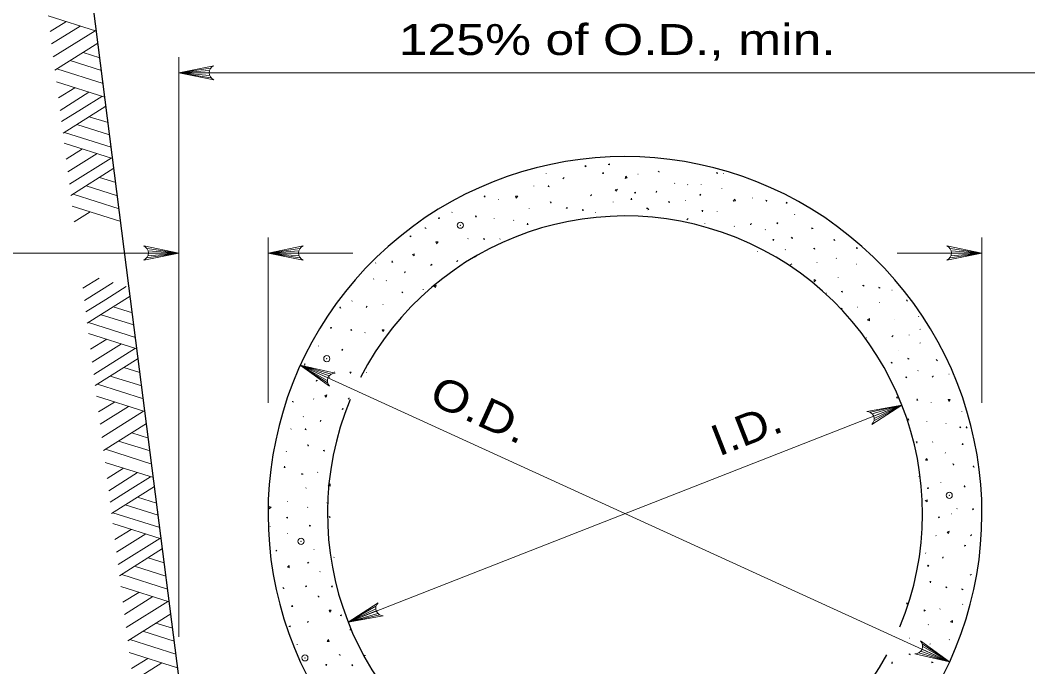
# Model space of a CAD drawing. Extents: x 1083.1 to 1117.1, y 697.4 to 741.4.
# Drawn here: x 1089.62 to 1094.7, y 722.98 to 726.24 of the extents above; entities that cross this region are included whole.
import ezdxf
from ezdxf.enums import TextEntityAlignment as Align

# ---------------------------------------------------------------- set-up
doc = ezdxf.new("R2010")
doc.units = 0
doc.header["$LTSCALE"] = 0.062
doc.header["$PDMODE"] = 32
doc.header["$PDSIZE"] = 0.031
doc.layers.add('1', color=7, linetype='Continuous', lineweight=13)

msp = doc.modelspace()

# ---------------------------------------------------------------- linework, layer by layer
at = {"layer": '1'}
for p, q in [((1090.00183, 726.18108), (1089.758, 726.25825)), ((1089.84842, 726.22842), (1089.76825, 726.17892)), ((1089.91933, 726.20692), (1089.776, 726.1175)), ((1089.995, 726.18325), (1089.7845, 726.051)), ((1090.0095, 726.12108), (1089.793, 725.9845)), ((1090.01892, 726.0475), (1089.93492, 726.07375)), ((1090.02725, 725.98242), (1089.869, 726.03267)), ((1090.41717, 723.12875), (1090.41717, 726.05008)), ((1090.03558, 725.91667), (1089.80308, 725.99083)), ((1090.57733, 725.99383), (1090.41717, 725.97142)), ((1090.57192, 725.98275), (1090.41717, 725.97142)), ((1090.41717, 725.97142), (1094.915, 725.97142)), ((1090.57025, 725.97142), (1090.41717, 725.97142)), ((1090.57308, 725.95708), (1090.41717, 725.97142)), ((1090.57925, 725.94667), (1090.41717, 725.97142)), ((1090.04442, 725.848), (1089.80058, 725.92517)), ((1089.89375, 725.89567), (1089.81092, 725.84442)), ((1089.96417, 725.87342), (1089.81892, 725.78158)), ((1090.02933, 725.85267), (1089.92708, 725.78808)), ((1089.92708, 725.78808), (1089.82608, 725.72508)), ((1090.05, 725.80375), (1089.8335, 725.66783)), ((1090.0685, 725.65933), (1089.90275, 725.71092)), ((1090.06067, 725.72008), (1089.96467, 725.75)), ((1090.0765, 725.59642), (1089.84033, 725.67092)), ((1090.08375, 725.53925), (1089.83933, 725.61633)), ((1089.93233, 725.5875), (1089.85017, 725.53642)), ((1090.00583, 725.56417), (1089.8585, 725.472)), ((1090.07617, 725.54192), (1089.86642, 725.40983)), ((1090.09, 725.49075), (1089.87358, 725.35342)), ((1092.26942, 725.464), (1092.26875, 725.462)), ((1092.73292, 725.45967), (1092.73092, 725.46033)), ((1093.16183, 725.46317), (1093.16267, 725.46167)), ((1093.16267, 725.46167), (1093.163, 725.46283)), ((1090.10767, 725.352), (1089.94958, 725.40158)), ((1090.09917, 725.41917), (1090.01742, 725.44433)), ((1092.20708, 725.40167), (1092.20642, 725.39967)), ((1092.91617, 725.41508), (1092.91808, 725.41425)), ((1092.98142, 725.40608), (1092.98208, 725.40808)), ((1093.05008, 725.40625), (1093.05075, 725.40817)), ((1090.11608, 725.28625), (1089.88442, 725.35983)), ((1093.15392, 725.38625), (1093.15475, 725.38817)), ((1090.12425, 725.22267), (1089.8805, 725.29975)), ((1092.02908, 725.33508), (1092.02833, 725.33308)), ((1092.6065, 725.31925), (1092.60583, 725.32125)), ((1092.971, 725.32525), (1092.97175, 725.32725)), ((1093.3085, 725.33933), (1093.30917, 725.34133)), ((1089.97075, 725.26983), (1089.89058, 725.22042)), ((1091.79392, 725.26683), (1091.79458, 725.26875)), ((1092.18358, 725.28817), (1092.18283, 725.28625)), ((1092.51875, 725.26792), (1092.51675, 725.26725)), ((1092.78142, 725.28075), (1092.78625, 725.2825)), ((1093.13042, 725.27275), (1093.13117, 725.27475)), ((1093.52108, 725.25625), (1093.52175, 725.25825)), ((1092.00742, 725.23775), (1092.00658, 725.23583)), ((1092.10383, 725.22725), (1092.10533, 725.2285)), ((1093.06808, 725.21042), (1093.06875, 725.21242)), ((1093.21875, 725.1985), (1093.21717, 725.19725)), ((1093.37492, 725.18133), (1093.37342, 725.18008)), ((1090.86692, 724.30833), (1090.86692, 725.14183)), ((1091.87467, 725.13483), (1091.87542, 725.13675)), ((1092.03608, 725.133), (1092.03675, 725.135)), ((1094.46525, 724.30833), (1094.46525, 725.14183)), ((1090.41717, 725.06317), (1087.8435, 725.06317)), ((1090.255, 725.03842), (1090.41717, 725.06317)), ((1090.25692, 725.08558), (1090.41717, 725.06317)), ((1090.26117, 725.04875), (1090.41717, 725.06317)), ((1090.26233, 725.0745), (1090.41717, 725.06317)), ((1090.264, 725.06317), (1090.41717, 725.06317)), ((1091.02717, 725.08558), (1090.86692, 725.06317)), ((1091.02175, 725.0745), (1090.86692, 725.06317)), ((1091.29375, 725.06317), (1090.86692, 725.06317)), ((1091.02008, 725.06317), (1090.86692, 725.06317)), ((1091.02292, 725.04875), (1090.86692, 725.06317)), ((1091.02908, 725.03842), (1090.86692, 725.06317)), ((1093.33392, 725.06925), (1093.33475, 725.07117)), ((1093.47517, 725.08108), (1093.474, 725.07958)), ((1094.03808, 725.06317), (1094.46525, 725.06317)), ((1094.30308, 725.03842), (1094.46525, 725.06317)), ((1094.305, 725.08558), (1094.46525, 725.06317)), ((1094.30925, 725.04875), (1094.46525, 725.06317)), ((1094.31042, 725.0745), (1094.46525, 725.06317)), ((1094.31208, 725.06317), (1094.46525, 725.06317)), ((1091.40983, 725.01358), (1091.40908, 725.01158)), ((1093.63325, 725.01458), (1093.63525, 725.01533)), ((1093.73058, 725.03625), (1093.7325, 725.03708)), ((1093.83533, 725.00767), (1093.83333, 725.00692)), ((1090.01608, 724.93717), (1089.93325, 724.88583)), ((1090.0865, 724.91483), (1089.94133, 724.823)), ((1090.15167, 724.89417), (1090.04942, 724.8295)), ((1091.3995, 724.93267), (1091.39875, 724.93075)), ((1091.46475, 724.92375), (1091.46275, 724.92442)), ((1093.74108, 724.93983), (1093.73983, 724.93833)), ((1090.17242, 724.84517), (1089.95583, 724.70933)), ((1091.64792, 724.87917), (1091.64992, 724.8785)), ((1093.68017, 724.86008), (1093.68208, 724.86092)), ((1094.0135, 724.87625), (1094.0115, 724.87558)), ((1090.04942, 724.8295), (1089.94858, 724.7665)), ((1090.183, 724.76167), (1090.087, 724.79142)), ((1091.28983, 724.8205), (1091.29133, 724.82158)), ((1091.44608, 724.80333), (1091.4475, 724.80442)), ((1093.95125, 724.81392), (1093.94925, 724.81325)), ((1090.19083, 724.70083), (1090.02508, 724.75233)), ((1093.83775, 724.79042), (1093.83575, 724.78958)), ((1094.146, 724.74433), (1094.14667, 724.74233)), ((1090.19883, 724.63792), (1089.96267, 724.71233)), ((1091.53433, 724.72908), (1091.53358, 724.72708)), ((1094.0255, 724.72567), (1094.02667, 724.72717)), ((1090.20617, 724.58075), (1089.96167, 724.65783)), ((1091.35625, 724.66242), (1091.35558, 724.6605)), ((1094.09892, 724.65142), (1094.09808, 724.6495)), ((1094.15483, 724.67908), (1094.153, 724.67825)), ((1090.05467, 724.629), (1089.97267, 724.57783)), ((1090.12817, 724.60567), (1089.98083, 724.5135)), ((1091.12108, 724.59417), (1091.12183, 724.59617)), ((1093.88458, 724.63592), (1093.88267, 724.63517)), ((1094.15475, 724.61042), (1094.15275, 724.60958)), ((1090.1985, 724.58342), (1089.98875, 724.45133)), ((1094.04275, 724.56942), (1094.04383, 724.57092)), ((1090.21233, 724.53217), (1089.99592, 724.39483)), ((1094.3025, 723.00258), (1091.02967, 724.49792)), ((1091.16908, 724.43458), (1091.02967, 724.49792)), ((1091.16575, 724.42033), (1091.02967, 724.49792)), ((1091.16708, 724.40833), (1091.02967, 724.49792)), ((1091.17533, 724.44425), (1091.02967, 724.49792)), ((1091.18483, 724.45208), (1091.02967, 724.49792)), ((1090.23008, 724.39342), (1090.07192, 724.443)), ((1090.2215, 724.46067), (1090.13983, 724.48592)), ((1091.17667, 724.43742), (1091.17517, 724.43625)), ((1091.20183, 724.46208), (1091.20258, 724.46408)), ((1091.36325, 724.46033), (1091.364, 724.46233)), ((1094.14283, 724.46917), (1094.1445, 724.47042)), ((1094.29908, 724.452), (1094.30058, 724.45325)), ((1090.2385, 724.32767), (1090.00675, 724.40133)), ((1090.24658, 724.26417), (1090.00283, 724.34125)), ((1090.09308, 724.31142), (1090.01292, 724.26192)), ((1090.16417, 724.28992), (1090.02083, 724.2005)), ((1091.09642, 724.32758), (1091.09842, 724.32692)), ((1091.27, 723.2035), (1094.062, 724.297)), ((1093.90208, 724.26067), (1094.062, 724.297)), ((1093.91158, 724.25325), (1094.062, 724.297)), ((1093.9195, 724.24092), (1094.062, 724.297)), ((1093.92108, 724.21742), (1094.062, 724.297)), ((1093.92208, 724.22975), (1094.062, 724.297)), ((1094.20942, 724.31117), (1094.20867, 724.30917)), ((1090.23983, 724.26608), (1090.02933, 724.13392)), ((1091.04517, 724.23983), (1091.04442, 724.23783)), ((1094.36383, 724.26425), (1094.36317, 724.26233)), ((1090.25417, 724.20408), (1090.03767, 724.06742)), ((1094.18775, 724.21383), (1094.18692, 724.21192)), ((1094.28408, 724.20333), (1094.28567, 724.20458)), ((1090.26367, 724.13042), (1090.17967, 724.15675)), ((1090.98275, 724.1775), (1090.98208, 724.1755)), ((1090.272, 724.06542), (1090.11367, 724.11575)), ((1094.21633, 724.10908), (1094.217, 724.11108)), ((1090.28042, 723.99967), (1090.04783, 724.07383)), ((1090.95925, 724.06392), (1090.9585, 724.062)), ((1094.28075, 724.05725), (1094.28, 724.05525)), ((1090.28908, 723.931), (1090.04533, 724.00817)), ((1090.13842, 723.97858), (1090.05558, 723.92742)), ((1090.20883, 723.95642), (1090.06367, 723.86442)), ((1090.274, 723.93558), (1090.17183, 723.87108)), ((1091.1185, 723.95792), (1091.11658, 723.95708)), ((1094.14675, 723.9365), (1094.14758, 723.9385)), ((1090.29475, 723.88675), (1090.07817, 723.75083)), ((1091.05767, 723.87817), (1091.05883, 723.87967)), ((1094.25808, 723.90592), (1094.25883, 723.90783)), ((1090.17183, 723.87108), (1090.07092, 723.808)), ((1090.3055, 723.80308), (1090.20933, 723.833)), ((1090.31317, 723.74233), (1090.14758, 723.79383)), ((1090.96333, 723.81025), (1090.96533, 723.81108)), ((1091.06808, 723.78167), (1091.06625, 723.78092)), ((1091.1655, 723.80342), (1091.1635, 723.80267)), ((1094.33892, 723.77383), (1094.33958, 723.77583)), ((1090.32125, 723.6795), (1090.08508, 723.75392)), ((1094.31367, 723.74908), (1094.31208, 723.74792)), ((1090.32858, 723.62217), (1090.084, 723.69925)), ((1090.177, 723.6705), (1090.095, 723.61933)), ((1090.2505, 723.64717), (1090.10317, 723.55492)), ((1090.32083, 723.62492), (1090.11108, 723.49275)), ((1090.96508, 723.649), (1090.96708, 723.64967)), ((1094.23342, 723.63942), (1094.23533, 723.63858)), ((1090.33475, 723.57358), (1090.11833, 723.43633)), ((1090.34383, 723.50217), (1090.26217, 723.52733)), ((1091.09717, 723.56825), (1091.09908, 723.56892)), ((1091.20058, 723.52992), (1091.19933, 723.52842)), ((1094.18217, 723.5515), (1094.18133, 723.5495)), ((1090.35242, 723.435), (1090.19425, 723.4845)), ((1090.36083, 723.36925), (1090.12917, 723.44283)), ((1091.12783, 723.45692), (1091.12975, 723.45767)), ((1090.36892, 723.30558), (1090.12517, 723.38275)), ((1090.21542, 723.35283), (1090.13525, 723.30342)), ((1090.2865, 723.33133), (1090.14317, 723.24192)), ((1090.36217, 723.30767), (1090.15167, 723.17542)), ((1091.41108, 723.28275), (1091.27, 723.2035)), ((1091.41008, 723.27042), (1091.27, 723.2035)), ((1094.2555, 723.26958), (1094.25358, 723.26883)), ((1094.36908, 723.29317), (1094.36708, 723.29242)), ((1090.37667, 723.2455), (1090.16017, 723.109)), ((1091.41267, 723.25933), (1091.27, 723.2035)), ((1091.42058, 723.24692), (1091.27, 723.2035)), ((1091.43008, 723.2395), (1091.27, 723.2035)), ((1090.386, 723.17192), (1090.302, 723.19825)), ((1094.19467, 723.18983), (1094.19575, 723.19133)), ((1090.40275, 723.04117), (1090.17025, 723.11525)), ((1090.39433, 723.10692), (1090.236, 723.15717)), ((1094.10042, 723.12208), (1094.10233, 723.12275)), ((1094.3025, 723.11517), (1094.3005, 723.11442)), ((1091.01425, 723.09133), (1091.01342, 723.08933)), ((1094.16317, 723.06625), (1094.3025, 723.00258)), ((1094.16533, 723.0925), (1094.3025, 723.00258)), ((1094.16658, 723.0805), (1094.3025, 723.00258)), ((1094.20517, 723.09342), (1094.20325, 723.09267)), ((1090.41142, 722.9725), (1090.16767, 723.04958)), ((1090.26083, 723.02017), (1090.178, 722.96883)), ((1094.14742, 723.04883), (1094.3025, 723.00258)), ((1094.157, 723.05667), (1094.3025, 723.00258)), ((1090.33125, 722.99783), (1090.186, 722.906))]:
    msp.add_line(p, q, dxfattribs=at)
at = {"layer": '1', "lineweight": 25}
msp.add_lwpolyline([(1090.41717, 722.92817), (1090.16583, 724.89717), (1089.94983, 726.58858)], dxfattribs=at)
at = {"layer": '1'}
for points in [[(1090.59417, 725.936), (1090.41717, 725.97142), (1090.59417, 726.00683)], [(1092.83917, 725.47083), (1092.83867, 725.47225), (1092.83367, 725.47633)], [(1092.35892, 725.44333), (1092.3575, 725.44275), (1092.35333, 725.43775)], [(1092.67025, 725.45), (1092.66667, 725.43833), (1092.67683, 725.44225), (1092.6705, 725.44992)], [(1092.49808, 725.35742), (1092.49742, 725.356), (1092.49242, 725.35183)], [(1092.61608, 725.38192), (1092.62775, 725.3855), (1092.62392, 725.37517), (1092.61617, 725.38167)], [(1092.82108, 725.36975), (1092.8225, 725.37042), (1092.82667, 725.37542)], [(1092.118, 725.3395), (1092.1255, 725.34942), (1092.1145, 725.34917), (1092.118, 725.33967)], [(1093.2195, 725.33492), (1093.212, 725.32508), (1093.223, 725.32525), (1093.21958, 725.33467)], [(1092.78642, 725.2825), (1092.7765, 725.29), (1092.77658, 725.28567)], [(1092.97858, 725.23108), (1092.98, 725.23167), (1092.98425, 725.23667)], [(1093.29767, 725.207), (1093.29908, 725.20758), (1093.30317, 725.21258)], [(1091.65825, 725.1915), (1091.65883, 725.19017), (1091.66383, 725.186)], [(1090.24017, 725.02775), (1090.41717, 725.06317), (1090.24017, 725.09858)], [(1091.04392, 725.02775), (1090.86692, 725.06317), (1091.04392, 725.09858)], [(1091.71675, 725.11017), (1091.72408, 725.12), (1091.71308, 725.11983), (1091.71658, 725.11033)], [(1094.28825, 725.02775), (1094.46525, 725.06317), (1094.28825, 725.09858)], [(1091.5945, 725.05617), (1091.60425, 725.04875), (1091.60417, 725.05975), (1091.59467, 725.05625)], [(1091.81767, 725.01975), (1091.81908, 725.02042), (1091.82317, 725.02525)], [(1093.50083, 725.00383), (1093.5015, 725.00517), (1093.5065, 725.00942)], [(1091.55967, 724.96892), (1091.55825, 724.96833), (1091.55417, 724.96342)], [(1091.71058, 724.88867), (1091.71425, 724.90042), (1091.70392, 724.89658), (1091.71042, 724.88883)], [(1093.62883, 724.92567), (1093.619, 724.91817), (1093.61908, 724.92917), (1093.62858, 724.92575)], [(1091.54158, 724.868), (1091.54217, 724.86658), (1091.54717, 724.86242)], [(1091.36708, 724.79483), (1091.36567, 724.79425), (1091.36158, 724.78925)], [(1094.09017, 724.82117), (1094.08883, 724.82183), (1094.08458, 724.82683)], [(1093.88908, 724.72483), (1093.89892, 724.73233), (1093.89867, 724.72133), (1093.88925, 724.72475)], [(1091.44525, 724.66692), (1091.45275, 724.67667), (1091.44175, 724.6765), (1091.44525, 724.66708)], [(1094.017, 724.64667), (1094.01642, 724.64533), (1094.01142, 724.64117)], [(1091.17617, 724.3925), (1091.02967, 724.49792), (1091.20542, 724.457)], [(1091.04942, 724.49967), (1091.05275, 724.49717), (1091.05267, 724.50692)], [(1094.24092, 724.52008), (1094.24033, 724.5215), (1094.23533, 724.52567)], [(1094.22025, 724.4435), (1094.21883, 724.44292), (1094.21467, 724.43792)], [(1091.15908, 724.33717), (1091.16267, 724.34883), (1091.15242, 724.345), (1091.15892, 724.33742)], [(1090.99008, 724.31642), (1090.99067, 724.31508), (1090.99567, 724.31092)], [(1091.27675, 724.33158), (1091.27533, 724.331), (1091.27108, 724.326)], [(1093.88433, 724.26508), (1094.062, 724.297), (1093.91025, 724.19925)], [(1094.29842, 724.31558), (1094.30583, 724.32542), (1094.29483, 724.32525), (1094.29833, 724.31583)], [(1091.13458, 724.21917), (1091.13317, 724.21858), (1091.129, 724.21358)], [(1094.18775, 724.02825), (1094.18033, 724.0185), (1094.19125, 724.01867), (1094.18783, 724.02808)], [(1091.16983, 723.89233), (1091.17967, 723.89983), (1091.17958, 723.88883), (1091.17008, 723.89225)], [(1090.8825, 723.78183), (1090.87275, 723.77433), (1090.87292, 723.78533), (1090.88233, 723.78183)], [(1094.17992, 723.81642), (1094.18975, 723.809), (1094.18958, 723.81992), (1094.18017, 723.8165)], [(1090.877, 723.68575), (1090.87725, 723.68525), (1090.87708, 723.68525)], [(1094.29608, 723.64892), (1094.29967, 723.66067), (1094.28942, 723.65675), (1094.29592, 723.64908)], [(1094.41375, 723.64325), (1094.41233, 723.64275), (1094.40817, 723.63775)], [(1090.90658, 723.56033), (1090.90708, 723.56175), (1090.91208, 723.56583)], [(1094.2715, 723.53083), (1094.27025, 723.53025), (1094.266, 723.52533)], [(1090.96425, 723.48075), (1090.97408, 723.48825), (1090.97383, 723.47725), (1090.96433, 723.48075)], [(1094.41075, 723.44492), (1094.41017, 723.4435), (1094.40517, 723.43933)], [(1090.94667, 723.3715), (1090.94608, 723.37283), (1090.94117, 723.377)], [(1091.11942, 723.33508), (1091.12, 723.33367), (1091.125, 723.32958)], [(1091.44775, 723.235), (1091.27, 723.2035), (1091.422, 723.30092)], [(1091.17775, 723.25367), (1091.18525, 723.2635), (1091.17425, 723.26342), (1091.17775, 723.25392)], [(1091.07125, 723.20625), (1091.06983, 723.20567), (1091.06575, 723.20075)], [(1091.27875, 723.16325), (1091.28008, 723.16383), (1091.28433, 723.16883)], [(1094.30692, 723.20417), (1094.31667, 723.2115), (1094.3165, 723.2005), (1094.30708, 723.204)], [(1091.17217, 723.11592), (1091.16475, 723.106), (1091.17575, 723.10617), (1091.17225, 723.11567)], [(1094.15625, 723.10833), (1094.3025, 723.00258), (1094.12683, 723.044)], [(1091.23067, 723.0345), (1091.23, 723.03583), (1091.22508, 723.04)]]:
    msp.add_lwpolyline(points, dxfattribs=at)
for points in [[(1092.47158, 725.50142), (1092.466, 725.50342), (1092.46525, 725.49808)], [(1092.58208, 725.51), (1092.58767, 725.508), (1092.58842, 725.51333)], [(1092.55608, 725.47), (1092.55808, 725.46442), (1092.55283, 725.46375)], [(1093.13017, 725.46242), (1093.13217, 725.468), (1093.12683, 725.46875)], [(1092.28092, 725.40317), (1092.27892, 725.39758), (1092.28425, 725.39675)], [(1091.95817, 725.35183), (1091.95617, 725.34617), (1091.9615, 725.3455)], [(1092.71317, 725.36708), (1092.71875, 725.36517), (1092.71958, 725.37042)], [(1093.04467, 725.36033), (1093.04275, 725.35467), (1093.048, 725.354)], [(1092.29283, 725.31408), (1092.29475, 725.31975), (1092.28958, 725.3205)], [(1092.69908, 725.33892), (1092.70092, 725.33333), (1092.69575, 725.33258)], [(1092.8885, 725.31558), (1092.89033, 725.32125), (1092.88508, 725.32192)], [(1093.37933, 725.32258), (1093.38133, 725.32825), (1093.376, 725.32892)], [(1093.48017, 725.31992), (1093.47825, 725.31433), (1093.48358, 725.31358)], [(1091.91392, 725.25175), (1091.912, 725.24617), (1091.91733, 725.24542)], [(1092.36883, 725.29133), (1092.37442, 725.29325), (1092.37508, 725.288)], [(1092.45783, 725.27942), (1092.45225, 725.27742), (1092.4515, 725.28275)], [(1093.05667, 725.27125), (1093.05858, 725.27683), (1093.05325, 725.27767)], [(1091.72808, 725.24283), (1091.72608, 725.23725), (1091.73142, 725.23658)], [(1092.17492, 725.21275), (1092.173, 725.20717), (1092.17833, 725.2065)], [(1093.43433, 725.20958), (1093.43633, 725.21517), (1093.431, 725.216)], [(1091.58917, 725.14783), (1091.58358, 725.14983), (1091.58292, 725.14458)], [(1093.61383, 725.18625), (1093.60825, 725.18442), (1093.6075, 725.18967)], [(1091.95608, 725.12925), (1091.958, 725.13483), (1091.95267, 725.1355)], [(1093.41408, 725.12542), (1093.416, 725.131), (1093.41075, 725.13175)], [(1093.5035, 725.14042), (1093.50908, 725.14242), (1093.50983, 725.13708)], [(1093.71658, 725.12975), (1093.72217, 725.13158), (1093.723, 725.12642)], [(1091.9165, 725.045), (1091.91092, 725.04683), (1091.91008, 725.04167)], [(1093.6165, 725.08542), (1093.62208, 725.08742), (1093.62283, 725.08217)], [(1093.83908, 725.08758), (1093.8335, 725.08567), (1093.83283, 725.09092)], [(1091.49242, 725.02317), (1091.4905, 725.01758), (1091.49583, 725.01675)], [(1091.69442, 725.00433), (1091.68883, 725.00633), (1091.68817, 725.001)], [(1093.86367, 724.89967), (1093.86933, 724.90158), (1093.87, 724.89633)], [(1093.75558, 724.86875), (1093.76117, 724.87067), (1093.76192, 724.8655)], [(1093.95267, 724.88767), (1093.94717, 724.88575), (1093.94633, 724.89108)], [(1091.23042, 724.79208), (1091.22842, 724.7865), (1091.23375, 724.78583)], [(1093.76225, 724.78175), (1093.75675, 724.77983), (1093.75592, 724.785)], [(1091.18458, 724.68192), (1091.1865, 724.68742), (1091.18117, 724.68817)], [(1091.28542, 724.67917), (1091.28342, 724.67358), (1091.28875, 724.67275)], [(1091.24117, 724.57908), (1091.23925, 724.57358), (1091.2445, 724.57275)], [(1094.01433, 724.51008), (1094.00875, 724.50808), (1094.008, 724.51342)], [(1094.0985, 724.53025), (1094.093, 724.52833), (1094.09217, 724.53367)], [(1091.28333, 724.45658), (1091.28525, 724.46208), (1091.27992, 724.46292)], [(1094.08358, 724.44092), (1094.08158, 724.43533), (1094.08683, 724.4345)], [(1091.11617, 724.42017), (1091.1105, 724.422), (1091.10983, 724.41683)], [(1094.03758, 724.33058), (1094.03958, 724.33617), (1094.03433, 724.33692)], [(1094.1385, 724.32792), (1094.13658, 724.32225), (1094.14175, 724.32158)], [(1091.24725, 724.27725), (1091.24167, 724.27925), (1091.24092, 724.27392)], [(1094.09433, 724.22783), (1094.09233, 724.22225), (1094.09758, 724.22142)], [(1094.35525, 724.18883), (1094.35325, 724.18325), (1094.35858, 724.1825)], [(1094.38767, 724.18808), (1094.38575, 724.1825), (1094.39092, 724.18175)], [(1091.05658, 724.179), (1091.05467, 724.17333), (1091.05992, 724.17258)], [(1091.0685, 724.08992), (1091.07042, 724.0955), (1091.06525, 724.09625)], [(1094.13642, 724.10533), (1094.13833, 724.11092), (1094.13308, 724.11158)], [(1094.3675, 724.10392), (1094.3655, 724.09833), (1094.37075, 724.0975)], [(1091.1445, 724.06717), (1091.15008, 724.069), (1091.15075, 724.06383)], [(1090.95058, 723.98858), (1090.94867, 723.983), (1090.954, 723.98217)], [(1094.3215, 723.99358), (1094.3235, 723.99917), (1094.31817, 723.99992)], [(1094.42242, 723.99092), (1094.42042, 723.98525), (1094.42575, 723.98458)], [(1091.04317, 723.94917), (1091.0375, 723.94733), (1091.03675, 723.9525)], [(1094.19233, 723.88192), (1094.19033, 723.87633), (1094.19567, 723.87567)], [(1094.37817, 723.89083), (1094.37625, 723.88525), (1094.38142, 723.88442)], [(1090.95958, 723.73042), (1090.96517, 723.73233), (1090.96583, 723.727)], [(1091.18217, 723.7325), (1091.17658, 723.7305), (1091.17583, 723.73583)], [(1094.25308, 723.73183), (1094.2475, 723.73383), (1094.24683, 723.7285)], [(1094.42025, 723.76833), (1094.42225, 723.77392), (1094.41692, 723.77458)], [(1091.08208, 723.68825), (1091.0765, 723.68633), (1091.07575, 723.69167)], [(1094.38425, 723.58892), (1094.37867, 723.59092), (1094.37783, 723.58558)], [(1091.07325, 723.5025), (1091.06758, 723.5005), (1091.06692, 723.50575)], [(1094.19358, 723.49067), (1094.19167, 723.48508), (1094.19692, 723.48433)], [(1091.05858, 723.38742), (1091.06058, 723.38183), (1091.05542, 723.381)], [(1091.18925, 723.38642), (1091.18725, 723.38083), (1091.19258, 723.38017)], [(1094.20542, 723.40158), (1094.20742, 723.40725), (1094.20225, 723.408)], [(1094.2815, 723.37883), (1094.28708, 723.38083), (1094.28783, 723.3755)], [(1094.3705, 723.36692), (1094.365, 723.36492), (1094.36417, 723.37025)], [(1090.98775, 723.28775), (1090.98583, 723.28217), (1090.99117, 723.2815)], [(1094.08758, 723.30025), (1094.08558, 723.29467), (1094.09092, 723.294)], [(1091.23025, 723.23633), (1091.23583, 723.23433), (1091.23667, 723.2395)], [(1094.18008, 723.26092), (1094.17458, 723.259), (1094.17375, 723.26433)], [(1090.97233, 723.18108), (1090.978, 723.17917), (1090.97875, 723.18433)], [(1091.35808, 723.03492), (1091.3525, 723.03683), (1091.35167, 723.03167)], [(1094.09658, 723.04217), (1094.10208, 723.044), (1094.10292, 723.03883)], [(1091.16075, 722.98317), (1091.16275, 722.98875), (1091.1575, 722.98942)], [(1091.29133, 722.98217), (1091.28933, 722.98775), (1091.29458, 722.98858)], [(1094.01225, 723.00258), (1094.01425, 722.99692), (1094.00892, 722.99625)], [(1094.219, 723.00008), (1094.2135, 722.99808), (1094.21275, 723.00333)]]:
    msp.add_lwpolyline(points, close=True, dxfattribs=at)
for centre, start, end in [((1090.60842, 725.97148), 112.08782, 247.91395), ((1090.22583, 725.0632), 292.08605, 67.91218), ((1091.05821, 725.0632), 112.08782, 247.91395), ((1094.27392, 725.0632), 292.08605, 67.91218), ((1091.20385, 724.41888), 87.68051, 223.50663), ((1093.88403, 724.22688), 313.57997, 89.4061), ((1091.44817, 723.27322), 133.44214, 269.26827), ((1094.12851, 723.08207), 267.51414, 43.34027)]:
    msp.add_arc(centre, 0.0382, start, end, dxfattribs=at)
at = {"layer": '1', "lineweight": 25}
for major_axis, start_param, end_param in [((1.79915, 0), 5.8086305, 9.8993328), ((1.79915, 0), 5.8086305, 9.8993328), ((1.49929, 0), 5.8920662, 8.9493934), ((1.49929, 0), 2.7486716, 5.7883795)]:
    msp.add_ellipse((1092.66607, 723.75022), major_axis=major_axis, ratio=0.999895, start_param=start_param, end_param=end_param, dxfattribs=at)
at = {"layer": '1'}
for p in [(1091.83608, 725.20308), (1091.16325, 724.5305), (1094.30033, 723.84217), (1091.03342, 723.61042), (1091.05283, 723.02292)]:
    msp.add_point(p, dxfattribs=at)

# ---------------------------------------------------------------- texts
at = {"layer": '1', "width": 1.25}
msp.add_text('125% of O.D., min.', height=0.156, dxfattribs=at).set_placement((1092.62721, 726.061), align=Align.CENTER)
at = {"layer": '1'}
for s, rotation, width, p in [('O.D.', 335.445, 1.2, (1091.90367, 724.20259)), ('I.D.', 21.388, 1.1, (1093.30576, 724.10199))]:
    msp.add_text(s, height=0.156, rotation=rotation, dxfattribs=dict(at, width=width)).set_placement(p, align=Align.CENTER)

doc.saveas('drawing.dxf')
